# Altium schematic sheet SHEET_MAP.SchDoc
size Tabloid; SheetNumber: 1; SheetTotal: 7
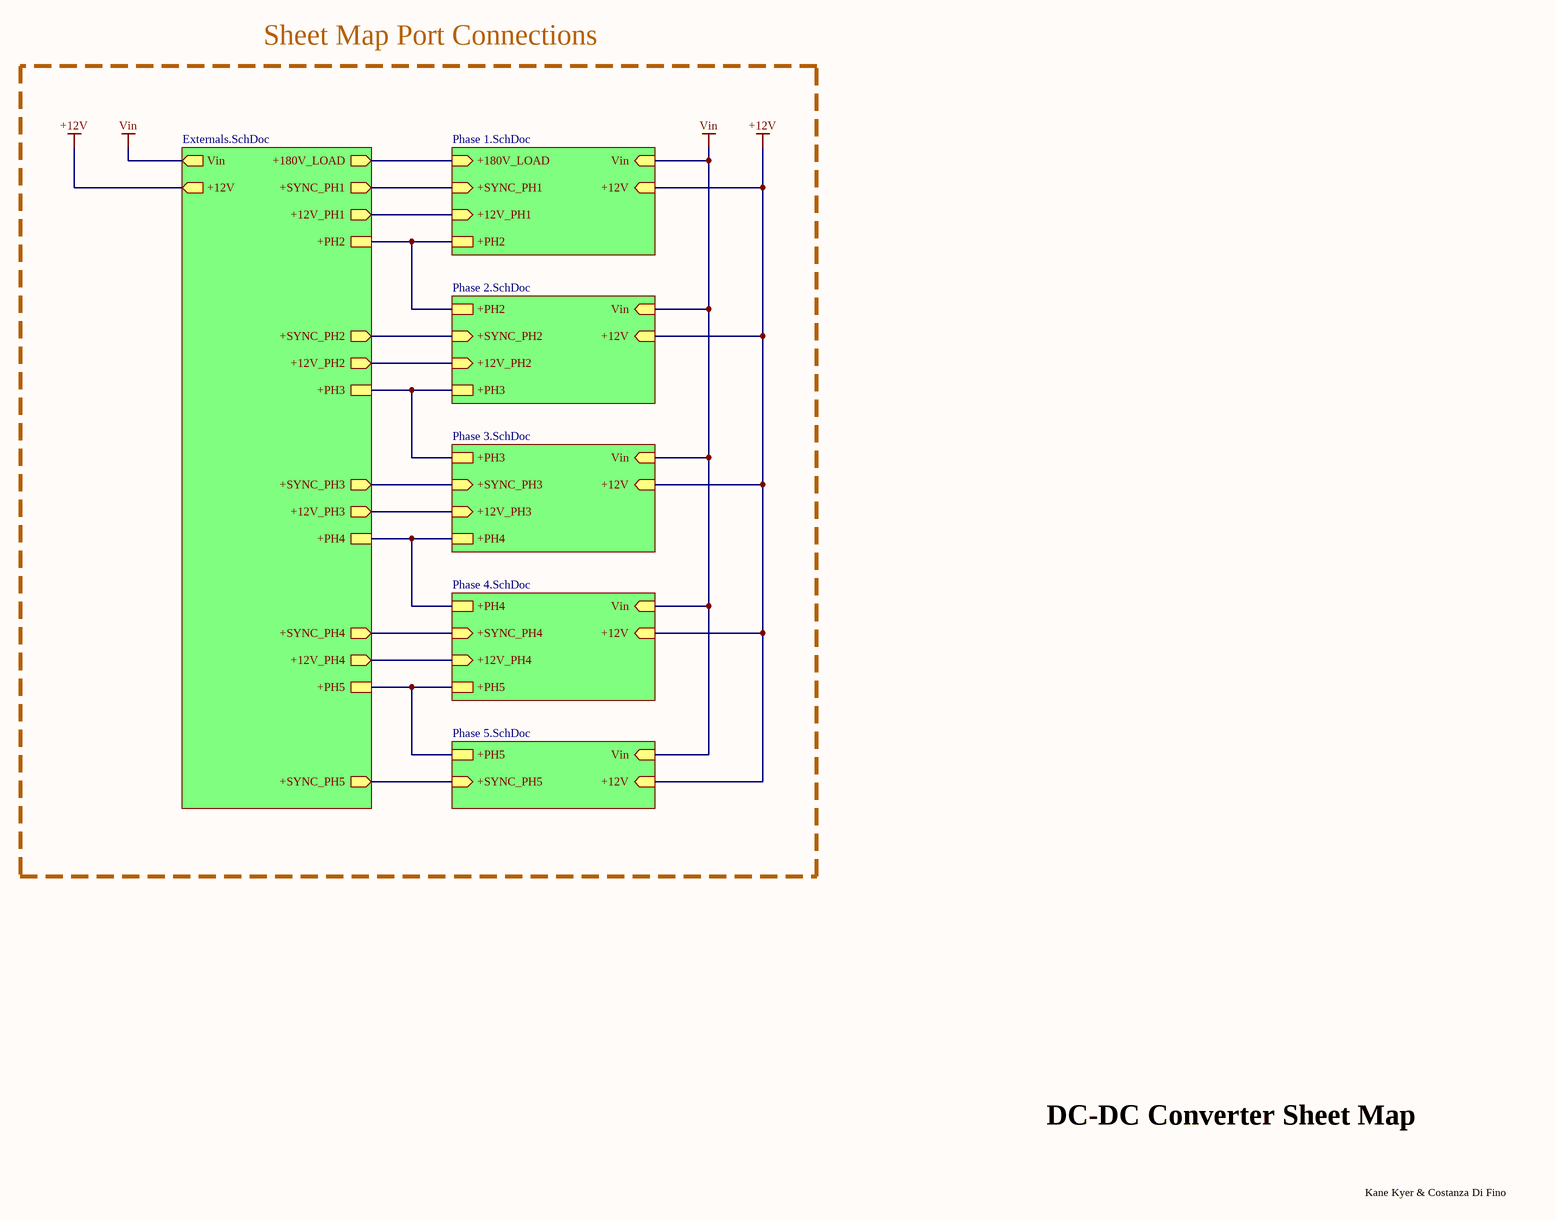
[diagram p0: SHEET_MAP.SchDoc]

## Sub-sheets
U_EXTERNAL = Externals.SchDoc: +SYNC_PH1 (out), +SYNC_PH2 (out), +SYNC_PH3 (out), +SYNC_PH4 (out), +SYNC_PH5 (out), +180V_LOAD (out), Vin (out), +12V (out), +12V_PH1 (out), +12V_PH2 (out), +12V_PH3 (out), +12V_PH4 (out), +PH2, +PH3, +PH4, +PH5
U_LTC3751_PH1 = Phase 1.SchDoc: +SYNC_PH1 (in), +180V_LOAD (in), Vin (in), +12V (in), +12V_PH1 (in), +PH2
U_LTC3751_PH2 = Phase 2.SchDoc: +SYNC_PH2 (in), Vin (in), +12V (in), +12V_PH2 (in), +PH3, +PH2
U_LTC3751_PH3 = Phase 3.SchDoc: +SYNC_PH3 (in), Vin (in), +12V (in), +12V_PH3 (in), +PH3, +PH4
U_LTC3751_PH4 = Phase 4.SchDoc: +SYNC_PH4 (in), Vin (in), +12V (in), +12V_PH4 (in), +PH4, +PH5
U_LTC3751_PH5 = Phase 5.SchDoc: +SYNC_PH5 (in), Vin (in), +12V (in), +PH5

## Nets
+12V: sheet U_EXTERNAL/+12V, sheet U_LTC3751_PH1/+12V, sheet U_LTC3751_PH2/+12V, sheet U_LTC3751_PH3/+12V, sheet U_LTC3751_PH4/+12V, sheet U_LTC3751_PH5/+12V
Vin: sheet U_EXTERNAL/Vin, sheet U_LTC3751_PH1/Vin, sheet U_LTC3751_PH2/Vin, sheet U_LTC3751_PH3/Vin, sheet U_LTC3751_PH4/Vin, sheet U_LTC3751_PH5/Vin
(unnamed): sheet U_EXTERNAL/+SYNC_PH1, sheet U_LTC3751_PH1/+SYNC_PH1
(unnamed): sheet U_EXTERNAL/+SYNC_PH2, sheet U_LTC3751_PH2/+SYNC_PH2  [a separate net that carries the same name]
(unnamed): sheet U_EXTERNAL/+SYNC_PH3, sheet U_LTC3751_PH3/+SYNC_PH3  [a separate net that carries the same name]
(unnamed): sheet U_EXTERNAL/+SYNC_PH4, sheet U_LTC3751_PH4/+SYNC_PH4  [a separate net that carries the same name]
(unnamed): sheet U_EXTERNAL/+SYNC_PH5, sheet U_LTC3751_PH5/+SYNC_PH5  [a separate net that carries the same name]
(unnamed): sheet U_EXTERNAL/+180V_LOAD, sheet U_LTC3751_PH1/+180V_LOAD  [a separate net that carries the same name]
(unnamed): sheet U_EXTERNAL/+12V_PH1, sheet U_LTC3751_PH1/+12V_PH1  [a separate net that carries the same name]
(unnamed): sheet U_EXTERNAL/+12V_PH2, sheet U_LTC3751_PH2/+12V_PH2  [a separate net that carries the same name]
(unnamed): sheet U_EXTERNAL/+12V_PH3, sheet U_LTC3751_PH3/+12V_PH3  [a separate net that carries the same name]
(unnamed): sheet U_EXTERNAL/+12V_PH4, sheet U_LTC3751_PH4/+12V_PH4  [a separate net that carries the same name]
(unnamed): sheet U_EXTERNAL/+PH2, sheet U_LTC3751_PH1/+PH2, sheet U_LTC3751_PH2/+PH2  [a separate net that carries the same name]
(unnamed): sheet U_EXTERNAL/+PH3, sheet U_LTC3751_PH2/+PH3, sheet U_LTC3751_PH3/+PH3  [a separate net that carries the same name]
(unnamed): sheet U_EXTERNAL/+PH4, sheet U_LTC3751_PH3/+PH4, sheet U_LTC3751_PH4/+PH4  [a separate net that carries the same name]
(unnamed): sheet U_EXTERNAL/+PH5, sheet U_LTC3751_PH4/+PH5, sheet U_LTC3751_PH5/+PH5  [a separate net that carries the same name]

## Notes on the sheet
- Sheet Map Port Connections
- DC-DC Converter Sheet Map
- Kane Kyer & Costanza Di Fino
